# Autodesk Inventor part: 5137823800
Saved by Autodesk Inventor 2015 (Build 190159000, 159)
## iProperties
Created: 2020-07
Part Number: 5137823800
Checked By: TraceParts S.A.
Material: Generic
Catalog Web Link: www.traceparts.com
Document SubType Name: Modeling
Designer: TraceParts
Density: 1 g/cm^3
Appearance: Default
Company: TraceParts S.A.
Author: TraceParts
REFERENCE: 5137823800
DESIGN: CVAT/4-2000/315 N D PTC 0,18KW (230/400V) 50Hz - 5137823800
SUPPLIER: Soler & Palau
TraceParts.PartNumber: 10-14122018-105188
TraceParts.PartTitle: CVAT-N
TraceParts.InstanceId: 10-14122018-10518878G3MFULJB21MO5OV54XDL4TN
TraceParts.PartStatus: Published
TraceParts.PartVersion: 1.0.4
TRACEPARTS: TRACEPARTS
TraceParts.PartLanguage: en
TraceParts.ClassPath: SOLER_PALAU:10-14122018-105188
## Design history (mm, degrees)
feature "5137823800"
body "Solid1"
